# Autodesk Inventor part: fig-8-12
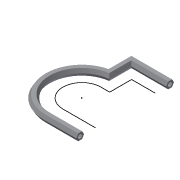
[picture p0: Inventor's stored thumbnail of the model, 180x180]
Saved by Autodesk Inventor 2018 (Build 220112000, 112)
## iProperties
Created: 2004-05
Part Number: fig-8-12
Document SubType Name: Modeling
Designer: CADCIM Technologies
Manufacturer: Standard
Standards Organization: Custom
Density: 1 g/cm^3
Material: Generic
Appearance: Default
Author: CADCIM Technologies
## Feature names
1. Sweep5
## Parameters: d4 = 0, d5 = 0
